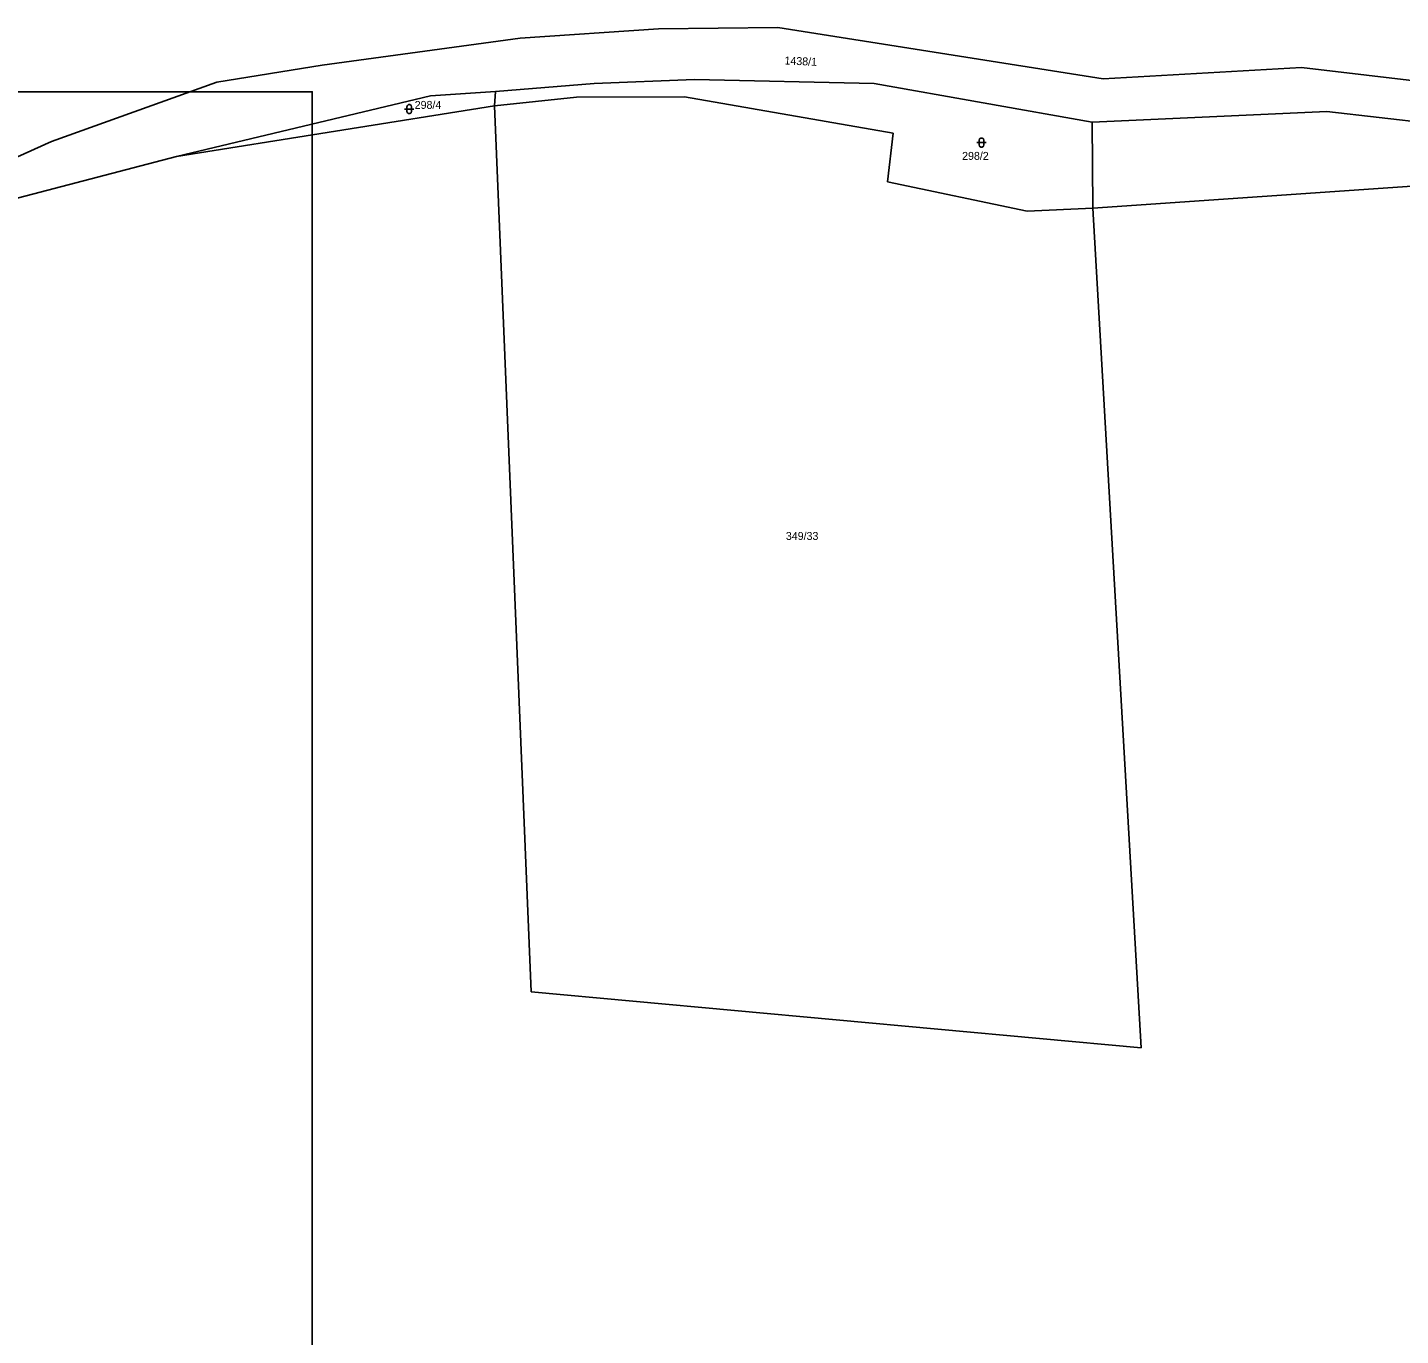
# Model space of a CAD drawing. Extents: x -852001 to -842497, y -1063614 to -1052182.
# Drawn here: x -848609.9 to -848316.1, y -1056471.5 to -1056191.5 of the extents above; entities that cross this region are included whole.
import ezdxf

# ---------------------------------------------------------------- set-up
doc = ezdxf.new("R2010")
doc.units = 0
for name, color, linetype in [('Default', 7, 'Continuous'), ('KN_HRANICE', 7, 'Continuous'), ('KN_KULTURY', 7, 'Continuous'), ('KN_PARCELY', 7, 'Continuous'), ('LEGENDA', 7, 'Continuous')]:
    doc.layers.add(name, color=color, linetype=linetype)

# ---------------------------------------------------------------- blocks, each defined once
blk = doc.blocks.new('316')
at = {"layer": 'Default'}
for points in [[(-1, 1), (0.27, 1), (1, 1)], [(-0.5, 1.5), (-0.4, 1.79), (-0.15, 1.97), (0.16, 1.97), (0.41, 1.79), (0.51, 1.5), (0.51, 0.5), (0.41, 0.21), (0.16, 0.03), (-0.15, 0.03), (-0.4, 0.21), (-0.5, 0.5), (-0.5, 1.5)]]:
    blk.add_lwpolyline(points, dxfattribs=at)

msp = doc.modelspace()

# ---------------------------------------------------------------- linework, layer by layer
at = {"layer": 'KN_HRANICE'}
for p, q in [((-848474.86, -1056191.76), (-848504.46, -1056193.78)), ((-848474.86, -1056191.76), (-848504.46, -1056193.78)), ((-848449.34, -1056191.49), (-848474.86, -1056191.76)), ((-848449.34, -1056191.49), (-848474.86, -1056191.76)), ((-848379.71, -1056202.48), (-848449.34, -1056191.49)), ((-848379.71, -1056202.48), (-848449.34, -1056191.49)), ((-848504.46, -1056193.78), (-848546.78, -1056199.58)), ((-848504.46, -1056193.78), (-848546.78, -1056199.58)), ((-848546.78, -1056199.58), (-848569.35, -1056203.22)), ((-848546.78, -1056199.58), (-848569.35, -1056203.22)), ((-848337.26, -1056200.03), (-848379.71, -1056202.48)), ((-848337.26, -1056200.03), (-848379.71, -1056202.48)), ((-848276.25, -1056207.32), (-848337.26, -1056200.03)), ((-848276.25, -1056207.32), (-848337.26, -1056200.03)), ((-848569.35, -1056203.22), (-848604.75, -1056215.87)), ((-848569.35, -1056203.22), (-848604.75, -1056215.87)), ((-848488.63, -1056203.5), (-848509.76, -1056205.2)), ((-848488.63, -1056203.5), (-848509.76, -1056205.2)), ((-848467.17, -1056202.6), (-848488.63, -1056203.5)), ((-848467.17, -1056202.6), (-848488.63, -1056203.5)), ((-848428.67, -1056203.49), (-848467.17, -1056202.6)), ((-848428.67, -1056203.49), (-848467.17, -1056202.6)), ((-848382.06, -1056211.75), (-848428.67, -1056203.49)), ((-848382.06, -1056211.75), (-848428.67, -1056203.49)), ((-848523.65, -1056206.1), (-848577.95, -1056219.08)), ((-848523.65, -1056206.1), (-848577.95, -1056219.08)), ((-848509.76, -1056205.2), (-848523.65, -1056206.1)), ((-848509.76, -1056205.2), (-848523.65, -1056206.1)), ((-848509.91, -1056208.25), (-848509.76, -1056205.2)), ((-848509.91, -1056208.25), (-848509.76, -1056205.2)), ((-848492.39, -1056206.44), (-848509.91, -1056208.25)), ((-848492.39, -1056206.44), (-848509.91, -1056208.25)), ((-848469.27, -1056206.37), (-848492.39, -1056206.44)), ((-848469.27, -1056206.37), (-848492.39, -1056206.44)), ((-848424.62, -1056214.13), (-848469.27, -1056206.37)), ((-848424.62, -1056214.13), (-848469.27, -1056206.37)), ((-848577.95, -1056219.08), (-848509.91, -1056208.25)), ((-848577.95, -1056219.08), (-848509.91, -1056208.25)), ((-848509.91, -1056208.25), (-848502.11, -1056397.92)), ((-848509.91, -1056208.25), (-848502.11, -1056397.92)), ((-848331.84, -1056209.5), (-848382.06, -1056211.75)), ((-848331.84, -1056209.5), (-848382.06, -1056211.75)), ((-848381.91, -1056230.16), (-848382.06, -1056211.75)), ((-848381.91, -1056230.16), (-848382.06, -1056211.75)), ((-848267.24, -1056216.92), (-848331.84, -1056209.5)), ((-848267.24, -1056216.92), (-848331.84, -1056209.5)), ((-848425.83, -1056224.53), (-848424.62, -1056214.13)), ((-848425.83, -1056224.53), (-848424.62, -1056214.13)), ((-848604.75, -1056215.87), (-848639.31, -1056231.64)), ((-848604.75, -1056215.87), (-848639.31, -1056231.64)), ((-848577.95, -1056219.08), (-848618.09, -1056229.6)), ((-848577.95, -1056219.08), (-848618.09, -1056229.6)), ((-848395.97, -1056230.81), (-848425.83, -1056224.53)), ((-848395.97, -1056230.81), (-848425.83, -1056224.53)), ((-848381.91, -1056230.16), (-848303.3, -1056224.79)), ((-848381.91, -1056230.16), (-848303.3, -1056224.79)), ((-848381.91, -1056230.16), (-848395.97, -1056230.81)), ((-848381.91, -1056230.16), (-848395.97, -1056230.81)), ((-848371.59, -1056409.89), (-848381.91, -1056230.16)), ((-848371.59, -1056409.89), (-848381.91, -1056230.16)), ((-848502.11, -1056397.92), (-848371.59, -1056409.89)), ((-848502.11, -1056397.92), (-848371.59, -1056409.89))]:
    msp.add_line(p, q, dxfattribs=at)
at = {"layer": 'LEGENDA'}
msp.add_lwpolyline([(-849142.95, -1056625.24), (-848548.95, -1056625.24), (-848548.95, -1056205.24), (-849142.95, -1056205.24)], close=True, dxfattribs=at)

# ---------------------------------------------------------------- block references
at = {"layer": 'KN_KULTURY'}
for p in [(-848528.18, -1056209.97), (-848528.18, -1056209.97), (-848405.75, -1056217.13), (-848405.75, -1056217.13)]:
    msp.add_blockref('316', p, dxfattribs=at)

# ---------------------------------------------------------------- texts
at = {"layer": 'KN_PARCELY'}
msp.add_text('1438/1', height=1.7, rotation=357.354, dxfattribs=at).set_placement((-848447.92, -1056199.4))
msp.add_text('1438/1', height=1.7, rotation=357.354, dxfattribs=at).set_placement((-848447.92, -1056199.4))
for s, p in [('298/4', (-848527.01, -1056208.92)), ('298/4', (-848527.01, -1056208.92)), ('298/2', (-848409.88, -1056219.83)), ('298/2', (-848409.88, -1056219.83)), ('349/33', (-848447.59, -1056301.18)), ('349/33', (-848447.59, -1056301.18))]:
    msp.add_text(s, height=1.7, dxfattribs=at).set_placement(p)

doc.saveas('drawing.dxf')
